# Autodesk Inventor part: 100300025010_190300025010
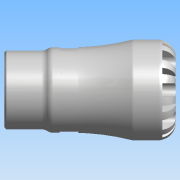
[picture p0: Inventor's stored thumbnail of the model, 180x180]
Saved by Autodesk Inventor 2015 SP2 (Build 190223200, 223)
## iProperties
Created: 2016-12
Part Number: 100300025010_190300025010
Material: PVC-Piping
Description: PLASSON FEMALE ADAPTOR 25X1" SERIES 1
Document SubType Name: Modeling
Designer: KIM
Mass: 664.223 g
Surface Area: 733.008 cm^2
Volume: 474.445 cm^3
Density: 1.4 g/cm^3
Appearance: Smooth - White
Author: KIM
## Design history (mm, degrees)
derived "1003.ipt"
feature "Solid1::1003.ipt"
tag "TaggingFeature1"
body "Solid1"
other parameters: "d1" = 20.16, "d2" = 25, "d3" = 31.25, "d4" = 47, "d6" = 48, "d8" = 39.95, "d13" = 6.3, "d14" = 6.3, "d15" = 0, "d17" = 360 deg, "d19" = 8 deg, "d20" = 0.5, "d21" = 0.5, "d22" = 8 deg, "d24" = 0, "d26" = 360 deg, "d32" = 4.7, "d33" = 4.7, "d39" = 0.90873, "d42" = 30.291, "d43" = 36.66, "d46" = 2.08333, "d47" = 21, "d48" = 28.77645, "d50" = 3.63, "d51" = 0.47, "d54" = 8.75, "d55" = 5.5, "d57" = 12.348, "d58" = 0, "d68" = 360 deg, "d72" = 0.5, "d74" = 0, "d76" = 7.4375, "d_" = 25, "E_" = 47, "l_" = 48, "Rp" = 30.291, "l_2" = 21, "d9" = 7.875, "d11" = 47, "d12" = 31.25, "d49" = 11
